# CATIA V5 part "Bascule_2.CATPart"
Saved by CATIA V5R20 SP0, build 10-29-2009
Part number: Bascule_2
Publications: "Corps_bascule_2", "Axe_pivot_bascule_2_point_G", "Axe_pivot_bascule_2_point_F", "Plan_ref", "Droite.4"
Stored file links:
  C:\Users\J\IAO_2012_jgossard\Bascule_2.CATPart
  C:\Users\J\IAO_2012_jgossard\squelette_mecanisme_presse.CATProduct

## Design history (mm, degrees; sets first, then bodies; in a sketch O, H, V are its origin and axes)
Set1
  Point1 "Point_F": linked copy from another document
  Point2 "Point_G": linked copy from another document
  Plane1 "Plan_ref": linked copy from another document
  Point3 "Point_fin_bascule_2": linked copy from another document
Body1 (main body)
  Line1 "Corps_bascule_2": type PtPt, FirstPoint Point1, SecondPoint Point2
  Line2 "Axe_pivot_bascule_2_point_G": type Normal, RefPoint Point2, RefSkin Plane1, Start 0, End 10
  Line3 "Axe_pivot_bascule_2_point_F": type Normal, RefPoint Point1, RefSkin Plane1, Start 0, End 10
  Line4: type PtPt, FirstPoint Point1, SecondPoint Point3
